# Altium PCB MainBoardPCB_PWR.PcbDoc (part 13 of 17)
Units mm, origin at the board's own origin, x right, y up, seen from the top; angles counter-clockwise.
Board outline 333.63 x 349.38 mm, 16 copper layers (L1, L2 (GND), L3 (Sign), L4 (GND), L5 (Sign), L6 (PWR/GND), L7(PWR/GND), L8 (PWR/GND), L9 (PWR/GND), L10 (PWR/GND), L11 (PWR/GND), L12 (Sign), L13 (GND), L14 (Sign), L15 (GND), L16), stack 2.503 mm thick; 2187 components, 1615 nets, 7987 pads, 1695 vias.
Unrouted connection lines stored in the file: 4757.
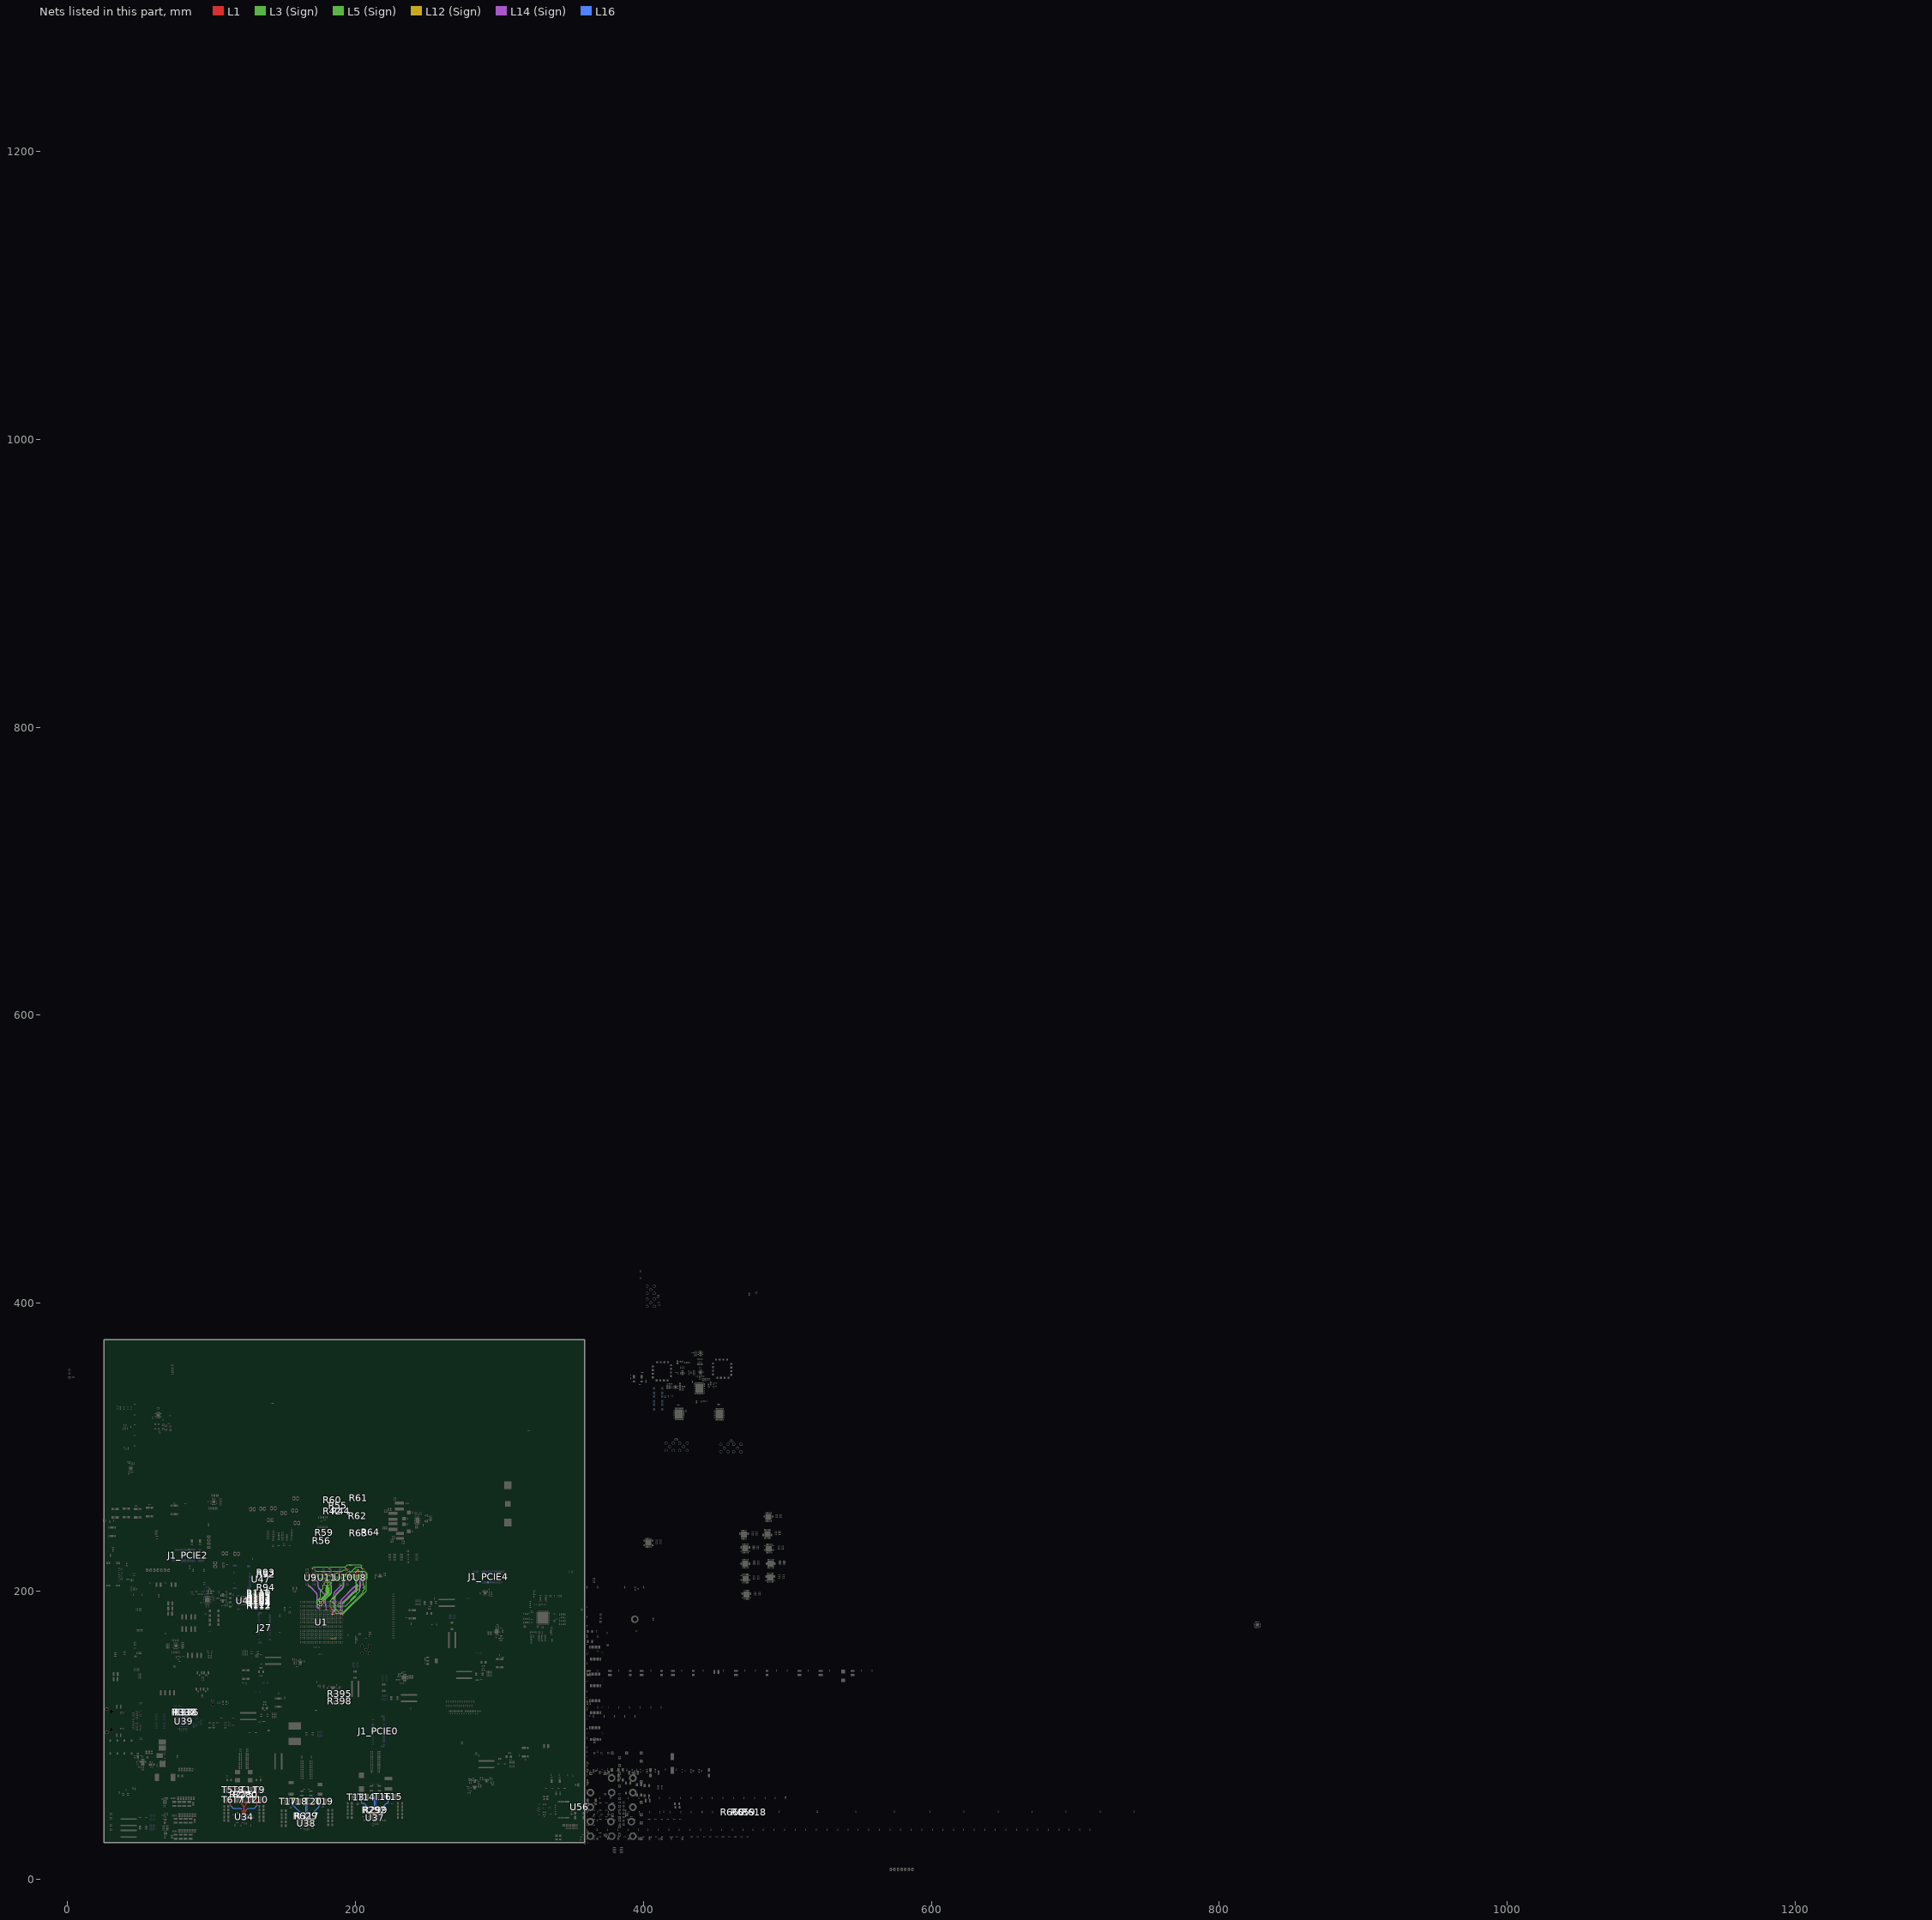
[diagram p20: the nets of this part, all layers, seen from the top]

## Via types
v1: diameter 0.5, hole 0.2, L1 to L16, 786 vias
v2: diameter 0.5/0.35/0.35/0.35/0.35/0.35/0.35/0.35/0.35/0.35/0.35/0.35/0.35/0.35/0.35/0.5 (per signal layer), hole 0.15, L1 to L16, tented both sides, 164 vias
v3: diameter 2.54, hole 1.02, L1 to L16, 152 vias
v4: diameter 0.5/0.35/0.35/0.35/0.35/0.35/0.35/0.35/0.35/0.35/0.35/0.35/0.35/0.35/0.35/0.5 (per signal layer), hole 0.2, L1 to L16, tented both sides, 100 vias
v5: diameter 0.45, hole 0.15, L1 to L16, 79 vias
v6: diameter 0.35/0/0.35 (per signal layer), hole 0.127, L1 to L3 (Sign), tented both sides, 78 vias
v7: diameter 0.45/0.45/0.45/0.45/0.45/0.45/0.45/0.45/0.45/0.45/0.45/0.45/0.45/0.45/0.45/0.45 (per signal layer), hole 0.15, L1 to L16, 65 vias
v8: diameter 0.4, hole 0.15, L1 to L16, 61 vias
v9: diameter 0.2, hole 0.1, L1 to L16, 35 vias
v10: diameter 0.5, hole 0.2, L1 to L16, tented both sides, 32 vias
v11: diameter 0.2/0/0.2 (per signal layer), hole 0.1, L1 to L3 (Sign), 28 vias
v12: diameter 0.4, hole 0.2, L1 to L16, 16 vias
v13: diameter 0.25, hole 0.2, L1 to L16, 16 vias
v14: diameter 0.3, hole 0.2, L1 to L16, 15 vias
v15: diameter 0.5/0.35/0.35/0.35/0.35/0.35/0.35/0.35/0.35/0.35/0.35/0.35/0.35/0.35/0.35/0.45 (per signal layer), hole 0.15, L1 to L16, tented both sides, 10 vias
v16: diameter 5, hole 3, L1 to L16, 9 vias
v17: diameter 0.2/0/0.2 (per signal layer), hole 0.1, L1 to L3 (Sign), tented both sides, 9 vias
v18: diameter 0.35/0/0.35 (per signal layer), hole 0.127, L1 to L3 (Sign), 7 vias
v19: diameter 0.35/0/0.35 (per signal layer), hole 0.127, L14 (Sign) to L16, tented both sides, 5 vias
v20: diameter 1.65, hole 1.65, L1 to L16, 4 vias
v21: diameter 1.15, hole 1.15, L1 to L16, 4 vias
v22: diameter 0.35, hole 0.127, L1 to L2 (GND), 2 vias
v23: diameter 0.4, hole 0.2, L1 to L16, tented both sides, 2 vias
v24: diameter 0.35, hole 0.127, L1 to L2 (GND), tented both sides, 2 vias
v25: diameter 0.508, hole 0.127, L1 to L2 (GND), 2 vias
v26: diameter 0.508, hole 0.127, L2 (GND) to L3 (Sign), 2 vias
v27: diameter 0.35, hole 0.127, L3 (Sign) to L6 (PWR/GND), tented both sides, 2 vias
v28: diameter 0.5, hole 0.2, L3 (Sign) to L6 (PWR/GND), tented both sides, 2 vias
v29: diameter 5.5, hole 3.5, L1 to L16, 1 vias
v30: diameter 0.45/0.45/0.45 (per signal layer), hole 0.15, L1 to L3 (Sign), 1 vias
v31: diameter 0.35/0.35/0.35 (per signal layer), hole 0.127, L1 to L3 (Sign), tented both sides, 1 vias
v32: diameter 0.45/0/0.45 (per signal layer), hole 0.15, L1 to L3 (Sign), tented both sides, 1 vias
v33: diameter 0.45/0/0.45 (per signal layer), hole 0.2, L14 (Sign) to L16, tented both sides, 1 vias
v34: diameter 0.35, hole 0.127, L2 (GND) to L3 (Sign), 1 vias

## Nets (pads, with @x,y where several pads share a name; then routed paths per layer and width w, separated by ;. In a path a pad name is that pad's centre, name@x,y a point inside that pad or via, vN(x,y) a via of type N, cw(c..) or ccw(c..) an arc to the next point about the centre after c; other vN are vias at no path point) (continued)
DDR4_DQ56: U1.R30 U11.A3 | length 13.3
  L1 w0.116: U1.R30@175.927,192.927 v6(175.927,193.616) ; v6(181.467,203.052) 181.47,203.052 U11.A3@181.866,203.448
  L3 (Sign) w0.092: v6(175.927,193.616) 175.976,193.666 176.222,193.666 181.7,199.144 181.7,202.818 v6(181.467,203.052)
DDR4_DQ57: U1.T30 U11.B5 | length 22.9
  L1 w0.116: v6(176.44,193.414) U1.T30@176.927,192.927 ; U11.B5@177.863,204.229 178.26,204.625 v6(178.262,204.625)
  L3 (Sign) w0.092: v6(176.44,193.414) 175.976,192.951 175.404,192.951 175.044,193.311 175.044,193.662 175.553,194.171 176.185,194.171 180.933,198.919 180.933,205.698 179.983,206.648 178.975,206.648 178.714,206.388 178.714,205.077 v6(178.262,204.625)
DDR4_DQ58: U1.P30 U11.C3 | length 15.6
  L1 w0.116: U1.P30@174.927,192.927 v6(175.414,193.414) ; v6(181.467,204.652) 181.47,204.652 U11.C3@181.866,205.048
  L3 (Sign) w0.092: v6(175.414,193.414) 175.414,193.727 175.666,193.979 176.264,193.979 181.508,199.223 181.508,202.248 181.146,202.61 181.146,204.331 v6(181.467,204.652)
DDR4_DQ59: U1.P29 U11.C4 | length 16.9
  L1 w0.116: v6(174.44,192.414) U1.P29@174.927,191.927 ; U11.C4@178.666,205.048 v6(179.063,204.649) v6(179.063,204.649)
  L3 (Sign) w0.092: v6(174.44,192.414) 174.44,192.969 174.649,193.178 174.649,193.856 175.358,194.565 176.036,194.565 180.409,198.938 180.409,203.303 v6(179.063,204.649)
DDR4_DQ60: U1.T28 U11.C2 | length 16.9
  L1 w0.116: U1.T28@176.927,190.927 v6(177.414,191.414) ; U11.C2@182.666,205.048 v6(183.063,204.649) v6(183.063,204.649)
  L3 (Sign) w0.092: v6(177.414,191.414) 177.836,191.836 177.836,192.859 177.703,192.991 177.703,193.727 183.063,199.087 v6(183.063,204.649)
DDR4_DQ61: U1.T27 U11.C5 | length 20.2
  L1 w0.116: v6(176.44,190.414) U1.T27@176.927,189.927 ; v6(177.467,204.652) 177.47,204.652 U11.C5@177.866,205.048
  L3 (Sign) w0.092: v6(176.44,190.414) 176.119,190.093 175.307,190.093 174.86,190.54 173.754,190.54 173.531,190.763 173.531,190.768 173.518,190.782 173.518,191.404 173.339,191.583 173.339,193.469 175.64,195.769 175.64,200.239 177.467,202.067 v6(177.467,204.652)
DDR4_DQ62: U1.P27 U11.D3 | length 21.3
  L1 w0.116: U1.P27@174.927,189.927 v6(175.414,189.44) ; v6(181.467,205.452) 181.47,205.452 U11.D3@181.866,205.848
  L3 (Sign) w0.092: v6(175.414,189.44) 175.876,189.901 176.198,189.901 176.236,189.94 176.668,189.94 176.86,190.132 176.86,190.538 175.933,191.465 175.933,192.424 176.935,193.426 176.935,194.107 181.892,199.064 181.892,205.026 v6(181.467,205.452)
DDR4_DQ63: U1.R27 U11.D4 | length 21.6
  L1 w0.116: v6(175.44,190.414) U1.R27@175.927,189.927 ; U11.D4@178.666,205.848 179.063,206.244 v6(179.065,206.244)
  L3 (Sign) w0.092: 175.044,191.25 175.044,190.81 v6(175.44,190.414) ; 175.044,191.25 175.044,192.964 174.841,193.167 174.841,193.777 175.438,194.373 176.116,194.373 180.734,198.991 180.734,205.626 179.921,206.439 179.259,206.439 v6(179.065,206.244)
DDR4_DQS_0_N: U1.AK21 U8.F3 | length 33
  L1 w0.116: U1.AK21@190.927,183.927 v4(191.414,183.44) ; v2(204.384,207.852) U8.F3@204.787,207.448
  L14 (Sign) w0.105: v4(191.414,183.44) 191.208,183.44 cw(c191.208,183.617) 191.031,183.617 191.031,190.662 cw(c193.571,190.662) 191.774,192.458 199.182,199.865 cw(c200.978,198.069) 200.978,200.609 200.991,200.609 ccw(c200.991,203.099) 202.752,201.338 202.787,201.374 ccw(c200.831,203.33) 203.597,203.33 203.597,207.712 cw(c204.025,207.712) 204.025,208.14 204.095,208.14 cw(c204.095,207.852) v2(204.384,207.852)
DDR4_DQS_0_P: U1.AJ21 U8.G3 | length 33.4
  L1 w0.116: U1.AJ21@189.927,183.927 v4(190.414,183.44) ; v2(204.384,208.652) U8.G3@204.787,208.248
  L14 (Sign) w0.105: v4(190.414,183.44) 190.621,183.44 ccw(c190.621,183.617) 190.798,183.617 190.798,190.662 cw(c193.569,190.662) 191.61,192.621 199.018,200.03 cw(c200.977,198.071) 200.977,200.841 200.99,200.841 ccw(c200.99,203.101) 202.588,201.503 202.621,201.536 ccw(c200.825,203.332) 203.365,203.332 203.365,207.712 cw(c204.025,207.712) 204.025,208.372 204.104,208.372 ccw(c204.104,208.652) v2(204.384,208.652)
DDR4_DQS_1_N: U1.AJ24 U8.A4 | length 23.7
  L1 w0.116: U1.AJ24@189.927,186.927 v4(190.414,187.414) ; U8.A4@201.587,203.448 v2(201.991,203.044)
  L14 (Sign) w0.105: v4(190.414,187.414) 190.179,187.414 cw(c190.179,187.563) 190.031,187.563 190.031,192.623 cw(c192.571,192.623) 190.774,194.419 198.913,202.558 cw(c200.709,200.762) 200.709,203.302 201.734,203.302 cw(c201.734,203.044) v2(201.991,203.044)
DDR4_DQS_1_P: U1.AH24 U8.B4 | length 24.1
  L1 w0.116: U1.AH24@188.927,186.927 v4(189.414,187.414) ; U8.B4@201.587,204.248 v2(201.991,203.844)
  L14 (Sign) w0.105: v4(189.414,187.414) 189.65,187.414 ccw(c189.65,187.563) 189.798,187.563 189.798,192.624 cw(c192.569,192.624) 190.61,194.583 198.749,202.722 cw(c200.708,200.763) 200.708,203.534 201.68,203.534 ccw(c201.68,203.844) v2(201.991,203.844)
DDR4_DQS_2_N: U1.AD21 U10.F3 | length 29.1
  L1 w0.116: v10(184.44,183.44) U1.AD21@184.927,183.927 ; v2(192.923,207.044) U10.F3@193.327,207.448
  L14 (Sign) w0.105: v10(184.44,183.44) 184.314,183.44 cw(c184.314,183.629) 184.125,183.629 184.125,184.417 cw(c185.385,184.417) 184.494,185.308 185.741,186.555 ccw(c185.011,187.286) 186.043,187.286 186.043,196.296 cw(c188.583,196.296) 186.787,198.092 191.365,202.67 ccw(c189.406,204.629) 192.176,204.629 192.176,206.845 cw(c192.672,206.845) 192.672,207.34 cw(c192.672,207.089) 192.923,207.089 v2(192.923,207.044)
DDR4_DQS_2_P: U1.AC21 U10.G3 | length 29.6
  L1 w0.116: v10(183.44,183.44) U1.AC21@183.927,183.927 ; v2(192.923,207.844) U10.G3@193.327,208.248
  L14 (Sign) w0.105: v10(183.44,183.44) 183.703,183.44 ccw(c183.703,183.629) 183.892,183.629 183.892,184.417 cw(c185.384,184.417) 184.329,185.472 185.577,186.719 ccw(c185.01,187.286) 185.811,187.286 185.811,196.297 cw(c188.582,196.297) 186.623,198.256 191.2,202.833 ccw(c189.404,204.63) 191.944,204.63 191.944,206.845 cw(c192.672,206.845) 192.672,207.572 ccw(c192.672,207.824) 192.923,207.824 v2(192.923,207.844)
DDR4_DQS_3_N: U1.AE24 U10.A4 | length 20.3
  L1 w0.116: v4(185.44,187.414) U1.AE24@185.927,186.927 ; U10.A4@190.127,203.448 v2(190.53,203.044)
  L14 (Sign) w0.105: v4(185.44,187.414) 185.24,187.414 cw(c185.24,187.599) 185.056,187.599 185.056,197.649 cw(c187.596,197.649) 185.8,199.445 189.24,202.886 cw(c190.335,201.792) 190.335,203.34 cw(c190.335,203.144) 190.53,203.144 v2(190.53,203.044)
DDR4_DQS_3_P: U1.AD24 U10.B4 | length 20.6
  L1 w0.116: v4(184.44,187.414) U1.AD24@184.927,186.927 ; U10.B4@190.127,204.248 v2(190.53,203.844)
  L14 (Sign) w0.105: v4(184.44,187.414) 184.639,187.414 ccw(c184.639,187.599) 184.823,187.599 184.823,197.65 cw(c187.594,197.65) 185.635,199.609 189.077,203.051 cw(c190.334,201.794) 190.334,203.572 ; 190.335,203.572 ccw(c190.335,203.767) 190.53,203.767 v2(190.53,203.844)
DDR4_DQS_4_N: U1.W25 U9.F3 | length 26.8
  L1 w0.116: v2(170.002,207.044) U9.F3@170.406,207.448 ; v10(179.44,187.44) U1.W25@179.927,187.927
  L14 (Sign) w0.105: v2(170.002,207.044) cw(c170.273,207.044) 170.273,207.315 172.272,207.315 cw(c172.272,205.537) 174.05,205.537 174.05,203.308 ccw(c176.82,203.308) 174.861,201.349 178.183,198.028 cw(c176.387,196.232) 178.927,196.232 178.927,191.109 ccw(c180.587,191.109) 179.413,189.935 179.414,189.933 cw(c178.457,188.976) 179.811,188.976 179.811,187.811 cw(c179.44,187.811) v10(179.44,187.44)
DDR4_DQS_4_P: U1.W24 U9.G3 | length 27.2
  L1 w0.116: v2(170.002,207.844) U9.G3@170.406,208.248 ; U1.W24@179.927,186.927 v10(180.414,187.414)
  L14 (Sign) w0.105: v2(170.002,207.844) ccw(c170.3,207.844) 170.3,207.547 172.272,207.547 cw(c172.272,205.537) 174.282,205.537 174.282,203.309 ccw(c176.822,203.309) 175.026,201.513 178.348,198.191 cw(c176.389,196.233) 179.159,196.233 179.159,191.111 ccw(c180.592,191.111) 179.579,190.098 179.581,190.096 cw(c178.464,188.979) 180.043,188.979 180.043,187.786 ccw(c180.414,187.786) v10(180.414,187.414)
DDR4_DQS_5_N: U1.R25 U9.A4 | length 21.2
  L1 w0.116: U9.A4@167.206,203.448 v2(167.609,203.044) ; v10(175.44,187.44) U1.R25@175.927,187.927
  L14 (Sign) w0.105: v2(167.609,203.044) cw(c167.854,203.044) 167.854,203.289 167.927,203.289 cw(c167.927,202.756) 168.304,203.133 172.557,198.88 cw(c170.761,197.084) 173.301,197.084 173.301,188.865 ccw(c173.85,188.865) 173.85,188.316 173.937,188.316 cw(c173.937,187.538) 174.486,188.088 174.488,188.086 ccw(c175.153,188.751) 175.153,187.811 175.171,187.811 cw(c175.171,187.542) 175.44,187.542 v10(175.44,187.44)
DDR4_DQS_5_P: U1.P25 U9.B4 | length 21.2
  L1 w0.116: U9.B4@167.206,204.248 v2(167.609,203.844) ; U1.P25@174.927,187.927 v10(175.414,188.414)
  L14 (Sign) w0.105: v2(167.609,203.844) 167.609,203.839 ccw(c167.927,203.839) 167.927,203.521 cw(c167.927,202.756) 168.468,203.297 172.721,199.044 cw(c170.763,197.085) 173.533,197.085 173.533,188.865 ccw(c173.85,188.865) 173.85,188.548 173.937,188.548 cw(c173.937,187.539) 174.65,188.252 ccw(c175.155,188.757) 175.155,188.043 175.171,188.043 ccw(c175.171,188.286) 175.414,188.286 v10(175.414,188.414)
DDR4_DQS_6_N: U1.V29 U11.F3 | length 21.4
  L1 w0.116: v1(178.44,192.414) U1.V29@178.927,191.927 ; v2(181.463,207.044) U11.F3@181.866,207.448
  L5 (Sign) w0.105: v1(178.44,192.414) 178.275,192.414 cw(c178.275,192.634) 178.056,192.634 178.056,193.815 cw(c178.576,193.815) 178.576,194.335 ccw(c178.576,195.953) 179.72,194.809 182.783,197.873 ccw(c180.824,199.832) 183.595,199.832 183.595,204.835 ccw(c182,204.835) 182,206.429 181.365,206.429 cw(c181.365,206.858) 180.937,206.858 180.937,207.086 cw(c181.178,207.086) 181.178,207.327 181.18,207.327 cw(c181.18,207.044) v2(181.463,207.044)
DDR4_DQS_6_P: U1.U29 U11.G3 | length 21.8
  L1 w0.116: v6(177.44,192.414) U1.U29@177.927,191.927 ; v2(181.463,207.844) U11.G3@181.866,208.248
  L5 (Sign) w0.105: v6(177.44,192.414) 177.605,192.414 ccw(c177.605,192.633) 177.824,192.633 177.824,193.816 cw(c178.575,193.816) 178.575,194.568 ccw(c178.575,195.956) 179.556,194.974 182.619,198.036 ccw(c180.823,199.833) 183.363,199.833 183.363,204.835 ccw(c182,204.835) 182,206.197 181.365,206.197 cw(c181.365,206.858) 180.705,206.858 180.705,207.086 cw(c181.178,207.086) 181.178,207.56 ccw(c181.178,207.844) v2@181.463,207.844
  other v1: 177.44,192.414
DDR4_DQS_7_N: U1.R29 U11.A4 | length 15.2
  L1 w0.116: v6(175.44,192.414) U1.R29@175.927,191.927 ; U11.A4@178.666,203.448 v2(179.07,203.044)
  L5 (Sign) w0.105: v6(175.44,192.414) ccw(c175.824,192.414) 175.824,192.031 175.927,192.031 ccw(c175.927,192.25) 176.147,192.25 176.147,192.909 cw(c178.918,192.909) 176.958,194.868 178.948,196.858 ccw(c177.152,198.654) 179.692,198.654 179.692,202.908 ccw(c179.286,202.908) 179.286,203.314 ccw(c179.286,203.098) 179.07,203.098 v2(179.07,203.044)
  other v1: 175.44,192.414
DDR4_DQS_7_P: U1.R28 U11.B4 | length 16
  L1 w0.116: v6(175.44,191.414) U1.R28@175.927,190.927 ; U11.B4@178.666,204.248 v2(179.07,203.844)
  L5 (Sign) w0.105: v6(175.44,191.414) cw(c175.824,191.414) 175.824,191.798 175.927,191.798 ccw(c175.927,192.25) 176.379,192.25 176.379,192.909 cw(c178.919,192.909) 177.123,194.705 179.113,196.695 ccw(c177.154,198.654) 179.924,198.654 179.924,202.908 ccw(c179.286,202.908) 179.286,203.546 cw(c179.286,203.763) 179.07,203.763 v2(179.07,203.844)
  other v1: 175.44,191.414
DDR4_DQS_8_N: U1.AA28
DDR4_DQS_8_P: U1.Y28
DDR4_DQS_ODT0: R44.1 U1.AB30 U8.K3 U9.K3 U10.K3 U11.K3 | length 93.1
  L1 w0.116: v2(170.002,210.244) U9.K3@170.406,210.648 ; v2(181.463,210.244) U11.K3@181.866,210.648 ; U1.AB30@182.927,192.927 v6(183.414,192.44) ; U10.K3@193.327,210.648 v2@193.516,210.459 ; U8.K3@204.787,210.648 v2(205.191,210.244)
  L5 (Sign) w0.092: v2(170.002,210.244) 170.318,210.244 170.729,210.655 171.727,210.655 172.084,211.012 172.434,211.012 174.481,208.966 179.565,208.966 179.603,209.004 179.882,209.004 181.122,210.244 v2(181.463,210.244) 182.096,210.244 182.507,210.655 183.793,210.655 185.38,209.067 191.346,209.067 191.954,209.676 192.28,209.676 192.849,210.244 193.239,210.244 193.65,210.655 194.648,210.655 194.867,210.436 194.867,210.022 195.224,209.664 196.736,209.664 197.241,209.664 cw(c197.241,209.575) 197.331,209.575 197.331,209.3 ccw(c197.42,209.3) 197.42,209.21 197.689,209.21 ccw(c197.689,209.3) 197.778,209.3 197.778,209.664 197.778,209.884 cw(c197.868,209.884) 197.868,209.973 198.137,209.973 cw(c198.137,209.884) 198.226,209.884 198.226,209.664 198.226,209.3 ccw(c198.316,209.3) 198.316,209.21 198.584,209.21 ccw(c198.584,209.3) 198.674,209.3 198.674,209.664 198.674,210.029 cw(c198.764,210.029) 198.764,210.119 199.032,210.119 cw(c199.032,210.029) 199.122,210.029 199.122,209.664 199.122,209.3 ccw(c199.211,209.3) 199.211,209.21 199.48,209.21 ccw(c199.48,209.3) 199.57,209.3 199.57,209.575 cw(c199.659,209.575) 199.659,209.664 199.793,209.664 200.959,210.83 204.605,210.83 v2(205.191,210.244)
  L3 (Sign) w0.092: v6(183.414,192.44) 183.774,192.799 184.509,192.799 184.735,192.573 184.735,191.869 185.953,190.652 185.953,190.095 185.599,189.742 185.414,189.742 185.226,189.553 185.226,189.288 185.811,188.703 185.811,188.136 188.33,185.617 191.909,185.617 205.135,198.844 205.135,200.054 206.388,201.307 206.388,201.861 206.388,202.159 ccw(c206.288,202.159) 206.288,202.258 205.743,202.258 cw(c205.743,202.358) 205.643,202.358 205.643,202.556 cw(c205.743,202.556) 205.743,202.655 206.288,202.655 ccw(c206.288,202.755) 206.388,202.755 206.388,203.052 206.388,203.251 205.511,204.127 205.511,209.062 205.702,209.253 205.702,209.733 v2(205.191,210.244)
  other v2: 193.516,210.458
DDR4_DQS_ODT1: U1.AC29
DDR4_PARITY: R42.1 U1.AB26 U8.T3 U9.T3 U10.T3 U11.T3 | length 91.1
  L1 w0.116: v2(170.002,215.852) U9.T3@170.406,215.448 ; v2(181.463,215.852) U11.T3@181.866,215.448 ; v6(182.44,189.414) U1.AB26@182.927,188.927 ; v2(192.923,215.852) U10.T3@193.327,215.448 ; v15(204.384,215.852) U8.T3@204.787,215.448
  L5 (Sign) w0.092: v2(170.002,215.852) 170.854,216.703 172.446,216.703 172.634,216.891 179.786,216.891 179.973,216.703 180.611,216.703 v2(181.463,215.852) 182.314,216.703 183.907,216.703 184.094,216.891 191.246,216.891 191.434,216.703 192.072,216.703 v2(192.923,215.852) 192.923,216.736 194.437,218.249 195.364,218.249 195.498,218.249 ccw(c195.498,218.339) 195.588,218.339 195.588,218.416 cw(c195.678,218.416) 195.678,218.506 195.946,218.506 cw(c195.946,218.416) 196.036,218.416 196.036,218.249 196.036,218.083 ccw(c196.125,218.083) 196.125,217.993 196.394,217.993 ccw(c196.394,218.083) 196.484,218.083 196.484,218.249 196.484,218.416 cw(c196.573,218.416) 196.573,218.506 196.842,218.506 cw(c196.842,218.416) 196.931,218.416 196.931,218.249 196.931,218.083 ccw(c197.021,218.083) 197.021,217.993 197.29,217.993 ccw(c197.29,218.083) 197.379,218.083 197.379,218.16 cw(c197.469,218.16) 197.469,218.249 199.098,218.249 203.721,218.249 204.384,217.587 v15(204.384,215.852)
  L3 (Sign) w0.092: v6(182.44,189.414) 182.709,189.684 182.709,193.373 183.524,194.187 183.789,194.452 ccw(c183.719,194.523) 183.789,194.593 183.677,194.705 cw(c183.747,194.775) 183.677,194.845 183.817,194.986 cw(c183.887,194.916) 183.958,194.986 184.14,194.803 184.544,194.399 ccw(c184.615,194.469) 184.685,194.399 184.825,194.539 ccw(c184.755,194.609) 184.825,194.68 184.421,195.084 184.238,195.267 cw(c184.308,195.337) 184.238,195.407 184.379,195.547 cw(c184.449,195.477) 184.519,195.547 184.702,195.365 185.067,194.999 ccw(c185.137,195.069) 185.208,194.999 185.348,195.139 ccw(c185.278,195.209) 185.348,195.28 184.982,195.645 184.8,195.828 cw(c184.87,195.898) 184.8,195.968 184.94,196.109 cw(c185.01,196.038) 185.08,196.109 185.263,195.926 185.608,195.582 ccw(c185.678,195.652) 185.748,195.582 185.888,195.722 ccw(c185.818,195.792) 185.888,195.862 185.544,196.207 185.361,196.389 cw(c185.431,196.46) 185.361,196.53 185.502,196.67 cw(c185.572,196.6) 185.642,196.67 185.754,196.558 ccw(c185.824,196.628) 185.895,196.558 186.105,196.768 186.245,196.909 191.467,202.13 191.467,209.68 192.176,210.39 192.176,211.402 192.736,211.962 195.66,211.962 200.589,216.891 203.344,216.891 v15(204.384,215.852)
DDR4_RAM_RST_N: R60.1 U1.AB25 U8.P1 U9.P1 U10.P1 U11.P1 | length 96.9
  L1 w0.116: U9.P1@172.006,213.848 v6(172.409,214.252) ; U1.AB25@182.927,187.927 v6(183.414,188.414) ; U11.P1@183.466,213.848 v6(183.87,214.252) ; U10.P1@194.927,213.848 v1(195.33,214.252) ; U8.P1@206.387,213.848 v2(206.791,213.444)
  L12 (Sign) w0.092: v1(195.33,214.252) 195.904,213.677 200.653,213.677 200.749,213.773 201.511,213.773 201.645,213.773 ccw(c201.645,213.862) 201.735,213.862 201.735,214.597 cw(c201.824,214.597) 201.824,214.687 202.093,214.687 cw(c202.093,214.597) 202.183,214.597 202.183,213.773 202.183,213.739 ccw(c202.272,213.739) 202.272,213.649 202.541,213.649 ccw(c202.541,213.739) 202.63,213.739 cw(c202.664,213.739) 202.664,213.773 203.111,213.773 206.193,213.773 206.521,213.444 v2(206.791,213.444)
  L3 (Sign) w0.092: v6(172.409,214.252) 172.755,213.906 183.524,213.906 v6(183.87,214.252) 184.33,213.792 191.033,213.792 191.033,213.864 191.818,214.648 194.934,214.648 v1(195.33,214.252) ; v6(183.414,188.414) 183.414,187.629 184.226,186.817 184.587,186.817 185.811,185.593 185.811,185.136 186.136,184.81 187.261,184.81 192.18,184.811 192.219,184.849 192.227,184.849 207.645,200.268 207.645,205.372 207.645,208.322 ccw(c207.546,208.322) 207.546,208.422 207.206,208.422 cw(c207.206,208.521) 207.107,208.521 207.107,208.719 cw(c207.206,208.719) 207.206,208.819 207.645,208.819 208.084,208.819 ccw(c208.084,208.918) 208.183,208.918 208.183,209.116 ccw(c208.084,209.116) 208.084,209.216 207.645,209.216 207.206,209.216 cw(c207.206,209.315) 207.107,209.315 207.107,209.513 cw(c207.206,209.513) 207.206,209.613 207.645,209.613 208.084,209.613 ccw(c208.084,209.712) 208.183,209.712 208.183,209.91 ccw(c208.084,209.91) 208.084,210.01 207.645,210.01 207.206,210.01 cw(c207.206,210.109) 207.107,210.109 207.107,210.307 cw(c207.206,210.307) 207.206,210.407 207.645,210.407 208.084,210.407 ccw(c208.084,210.506) 208.183,210.506 208.183,210.704 ccw(c208.084,210.704) 208.084,210.804 207.645,210.804 207.206,210.804 cw(c207.206,210.903) 207.107,210.903 207.107,211.101 cw(c207.206,211.101) 207.206,211.201 207.645,211.201 208.084,211.201 ccw(c208.084,211.3) 208.183,211.3 208.183,211.498 ccw(c208.084,211.498) 208.084,211.598 207.645,211.598 207.206,211.598 cw(c207.206,211.697) 207.107,211.697 207.107,211.895 cw(c207.206,211.895) 207.206,211.995 207.645,211.995 208.084,211.995 ccw(c208.084,212.094) 208.183,212.094 208.183,212.292 ccw(c208.084,212.292) 208.084,212.392 207.744,212.392 cw(c207.744,212.491) 207.645,212.491 207.645,212.59 v2(206.791,213.444)
DDR4_RAS: R59.1 U1.AH27 U8.L5 U9.L5 U10.L5 U11.L5 | length 90.7
  L1 w0.116: U9.L5@166.406,211.448 166.802,211.844 v2(166.805,211.844) ; U11.L5@177.866,211.448 178.263,211.844 v2(178.265,211.844) ; U1.AH27@188.927,189.927 v6(189.414,190.414) ; U10.L5@189.327,211.448 189.723,211.844 v2(189.726,211.844) ; U8.L5@200.787,211.448 201.184,211.844 v1(201.186,211.844)
  L12 (Sign) w0.092: 165.884,212.248 166.288,211.844 ; v2@166.802,211.844 166.288,211.844 ; v2(178.265,211.844) v2@178.507,211.844 ; v2(189.726,211.844) 189.988,211.844 ; v1(201.186,211.844) 200.745,211.844 200.241,211.341 200.107,211.341 ccw(c200.107,211.251) 200.018,211.251 200.018,211.15 cw(c199.928,211.15) 199.928,211.06 199.659,211.06 cw(c199.659,211.15) 199.57,211.15 199.57,211.341 199.57,211.532 ccw(c199.48,211.532) 199.48,211.621 199.212,211.621 ccw(c199.212,211.532) 199.122,211.532 199.122,211.43 cw(c199.032,211.43) 199.032,211.341 198.895,211.341 198.76,211.341 ccw(c198.76,211.251) 198.671,211.251 198.671,211.15 cw(c198.581,211.15) 198.581,211.06 198.313,211.06 cw(c198.313,211.15) 198.223,211.15 198.223,211.341 198.223,211.532 ccw(c198.133,211.532) 198.133,211.621 197.865,211.621 ccw(c197.865,211.532) 197.775,211.532 197.775,211.43 cw(c197.686,211.43) 197.686,211.341 197.294,211.341 191.552,211.341 191.017,211.876 190.728,212.165 190.309,212.165 189.988,211.844 ; 166.288,211.844 167.067,211.844 ; 166.288,211.844 v2(166.805,211.844) 167.067,211.844 ; 167.067,211.844 167.388,212.165 167.807,212.165 168.097,211.876 177.793,211.876 177.824,211.844 v2@178.507,211.844 ; v2@178.507,211.844 178.879,212.217 179.692,212.217 180.097,211.812 184.952,211.812 185.839,212.7 188.354,212.7 189.209,211.844 189.988,211.844
  L3 (Sign) w0.092: v6@189.459,190.459 189.459,190.839 189.46,190.84 189.46,190.917 189.462,190.919 189.462,191.101 189.762,191.401 189.762,191.461 190.202,191.901 190.468,191.901 192.179,191.901 192.375,192.098 192.456,192.411 192.729,192.684 193.407,193.362 ccw(c193.322,193.447) 193.407,193.532 193.272,193.667 cw(c193.357,193.752) 193.272,193.837 193.527,194.091 cw(c193.612,194.006) 193.697,194.091 193.916,193.871 193.957,193.83 ccw(c194.042,193.915) 194.127,193.83 194.382,194.085 ccw(c194.297,194.17) 194.382,194.255 194.341,194.296 194.121,194.516 cw(c194.206,194.601) 194.121,194.685 194.376,194.94 cw(c194.461,194.855) 194.545,194.94 194.765,194.72 194.806,194.679 ccw(c194.891,194.764) 194.976,194.679 195.231,194.934 ccw(c195.146,195.018) 195.231,195.103 195.19,195.145 194.97,195.364 cw(c195.055,195.449) 194.97,195.534 195.224,195.789 cw(c195.309,195.704) 195.394,195.789 195.614,195.569 195.656,195.527 ccw(c195.741,195.611) 195.826,195.527 196.081,195.781 ccw(c195.996,195.866) 196.081,195.951 196.038,195.993 195.819,196.213 cw(c195.903,196.298) 195.819,196.383 196.073,196.638 cw(c196.158,196.553) 196.243,196.638 196.463,196.418 196.506,196.375 ccw(c196.591,196.46) 196.676,196.375 196.93,196.629 ccw(c196.845,196.714) 196.93,196.799 196.887,196.842 196.667,197.062 cw(c196.752,197.147) 196.667,197.232 196.922,197.486 cw(c197.007,197.402) 197.092,197.486 197.312,197.267 197.356,197.223 ccw(c197.441,197.307) 197.526,197.223 197.78,197.477 ccw(c197.695,197.562) 197.78,197.647 197.736,197.691 197.516,197.911 cw(c197.601,197.996) 197.516,198.081 197.771,198.335 cw(c197.856,198.25) 197.941,198.335 198.161,198.115 198.205,198.071 ccw(c198.29,198.156) 198.375,198.071 198.63,198.325 ccw(c198.545,198.41) 198.63,198.495 198.585,198.54 198.365,198.76 cw(c198.45,198.845) 198.365,198.929 198.62,199.184 cw(c198.705,199.099) 198.789,199.184 199.009,198.964 199.055,198.918 ccw(c199.14,199.003) 199.225,198.918 199.479,199.173 ccw(c199.395,199.258) 199.479,199.343 199.434,199.389 199.403,199.419 cw(c199.488,199.504) 199.403,199.589 199.658,199.844 cw(c199.743,199.759) 199.828,199.844 199.858,199.813 200.257,199.415 ccw(c200.341,199.499) 200.426,199.415 200.681,199.669 ccw(c200.596,199.754) 200.681,199.839 200.367,200.153 cw(c200.452,200.237) 200.367,200.322 200.495,200.45 200.744,200.45 200.8,200.506 200.8,200.635 cw(c200.888,200.635) 200.888,200.723 201.301,200.723 ccw(c201.301,200.843) 201.421,200.843 201.421,201.203 ccw(c201.301,201.203) 201.301,201.323 200.8,201.323 200.352,201.323 cw(c200.352,201.443) 200.232,201.443 200.232,201.803 cw(c200.352,201.803) 200.352,201.923 200.8,201.923 201.301,201.923 ccw(c201.301,202.043) 201.421,202.043 201.421,202.403 ccw(c201.301,202.403) 201.301,202.524 200.8,202.524 200.352,202.524 cw(c200.352,202.644) 200.232,202.644 200.232,203.004 cw(c200.352,203.004) 200.352,203.124 200.8,203.124 201.301,203.124 ccw(c201.301,203.244) 201.421,203.244 201.421,203.604 ccw(c201.301,203.604) 201.301,203.724 200.92,203.724 cw(c200.92,203.844) 200.8,203.844 200.8,204.204 cw(c200.92,204.204) 200.92,204.324 201.301,204.324 ccw(c201.301,204.444) 201.421,204.444 201.421,204.804 ccw(c201.301,204.804) 201.301,204.924 200.92,204.924 cw(c200.92,205.044) 200.8,205.044 200.8,205.525 ccw(c200.8,205.577) 200.853,205.577 200.853,206.072 ccw(c200.8,206.072) 200.8,206.125 200.325,206.125 cw(c200.325,206.245) 200.205,206.245 200.205,206.605 cw(c200.325,206.605) 200.325,206.725 200.8,206.725 201.301,206.725 ccw(c201.301,206.845) 201.421,206.845 201.421,207.205 ccw(c201.301,207.205) 201.301,207.325 200.8,207.325 cw(c200.8,207.43) 200.695,207.43 200.695,207.821 cw(c200.8,207.821) 200.8,207.925 200.8,208.405 ccw(c200.68,208.405) 200.68,208.526 200.666,208.526 cw(c200.666,208.646) 200.546,208.646 200.546,209.006 cw(c200.666,209.006) 200.666,209.126 200.8,209.126 201.301,209.126 ccw(c201.301,209.246) 201.421,209.246 201.421,209.606 ccw(c201.301,209.606) 201.301,209.726 200.8,209.726 200.676,209.726 cw(c200.676,209.846) 200.556,209.846 200.556,210.206 cw(c200.676,210.206) 200.676,210.326 200.68,210.326 ccw(c200.68,210.446) 200.8,210.446 200.8,210.926 200.8,211.226 200.8,211.458 v1(201.186,211.844)
DDR4_TEN: R56.1 U8.N6 U9.N6 U10.N6 U11.N6
DDR4_WE: R55.1 U1.AG29 U8.L2 U9.L2 U10.L2 U11.L2 | length 94.3
  L1 w0.116: U9.L2@171.206,211.448 v2(171.609,211.044) ; U11.L2@182.666,211.448 v2(183.07,211.044) ; U1.AG29@187.927,191.927 188.341,191.513 v6(188.341,191.476) ; U10.L2@194.127,211.448 v2(194.53,211.044) ; v2(205.184,211.852) U8.L2@205.587,211.448
  L5 (Sign) w0.092: 170.445,210.642 170.847,211.044 v2(171.609,211.044) 171.659,211.094 171.895,211.094 172.005,211.204 172.514,211.204 174.522,209.196 179.802,209.196 181.33,210.723 181.596,210.723 181.629,210.756 181.975,210.756 182.263,211.044 ; v2(205.184,211.852) 204.846,211.852 204.016,211.022 200.879,211.022 200.436,210.578 200.431,210.578 200.253,210.58 198.373,210.597 cw(c198.374,210.666) 198.305,210.666 198.308,210.921 ccw(c198.218,210.922) 198.219,211.011 197.95,211.014 ccw(c197.949,210.924) 197.86,210.925 197.857,210.602 197.854,210.242 cw(c197.764,210.243) 197.763,210.153 197.494,210.156 cw(c197.495,210.245) 197.406,210.246 197.409,210.606 197.412,210.921 ccw(c197.322,210.922) 197.323,211.011 197.054,211.014 ccw(c197.054,210.924) 196.964,210.925 196.961,210.61 196.958,210.25 cw(c196.868,210.251) 196.868,210.162 196.599,210.164 cw(c196.6,210.254) 196.51,210.254 196.513,210.614 196.516,210.921 ccw(c196.427,210.922) 196.428,211.011 196.159,211.014 ccw(c196.158,210.924) 196.068,210.925 196.066,210.618 196.062,210.259 cw(c195.973,210.259) 195.972,210.17 195.703,210.172 cw(c195.704,210.262) 195.615,210.263 195.618,210.622 195.621,210.921 ccw(c195.531,210.922) 195.532,211.011 195.263,211.014 ccw(c195.262,210.924) 195.173,210.925 195.171,210.716 cw(c195.081,210.717) 195.081,210.627 194.946,210.628 v2(194.53,211.044) 193.723,211.044 193.458,210.779 193.112,210.779 192.2,209.867 185.032,209.867 183.855,211.044 v2(183.07,211.044) ; 182.263,211.044 v2(183.07,211.044) ; 182.263,211.044 v2(183.07,211.044)
  L3 (Sign) w0.092: v6(188.341,191.476) 188.45,191.476 188.093,191.119 188.093,190.957 187.865,190.729 187.865,189.715 187.927,189.652 187.927,189.198 188.107,189.018 189.649,189.018 189.86,189.23 189.86,189.599 190.122,189.86 193.421,189.86 196.414,192.854 196.525,192.964 cw(c196.595,192.894) 196.665,192.964 196.663,192.966 ; 196.663,192.967 ccw(c196.733,193.037) 196.803,192.967 196.943,193.107 ccw(c196.873,193.177) 196.943,193.247 196.876,193.315 196.521,193.669 cw(c196.592,193.739) 196.521,193.809 196.662,193.95 cw(c196.732,193.88) 196.802,193.95 197.156,193.596 197.224,193.528 ccw(c197.294,193.598) 197.364,193.528 197.505,193.668 ccw(c197.434,193.739) 197.505,193.809 197.437,193.876 197.083,194.231 cw(c197.153,194.301) 197.083,194.371 197.223,194.511 cw(c197.293,194.441) 197.364,194.511 197.718,194.157 197.785,194.089 ccw(c197.856,194.16) 197.926,194.089 198.066,194.23 ccw(c197.996,194.3) 198.066,194.37 197.998,194.438 197.644,194.792 cw(c197.715,194.862) 197.644,194.932 197.785,195.073 cw(c197.855,195.003) 197.925,195.073 198.279,194.719 198.347,194.651 ccw(c198.417,194.721) 198.487,194.651 198.628,194.791 ccw(c198.557,194.861) 198.628,194.932 198.56,194.999 198.206,195.353 cw(c198.276,195.424) 198.206,195.494 198.346,195.634 cw(c198.416,195.564) 198.487,195.634 198.841,195.28 198.906,195.215 ccw(c198.976,195.285) 199.046,195.215 199.187,195.355 ccw(c199.116,195.425) 199.187,195.495 199.121,195.561 198.767,195.915 cw(c198.837,195.985) 198.767,196.055 198.908,196.196 cw(c198.978,196.125) 199.048,196.196 199.402,195.841 199.467,195.776 ccw(c199.537,195.846) 199.608,195.776 199.748,195.917 ccw(c199.678,195.987) 199.748,196.057 199.683,196.122 199.329,196.476 cw(c199.399,196.546) 199.329,196.617 199.469,196.757 cw(c199.539,196.687) 199.609,196.757 199.964,196.403 200.034,196.333 ccw(c200.104,196.403) 200.174,196.333 200.314,196.473 ccw(c200.244,196.543) 200.314,196.613 cw(c200.385,196.684) 200.314,196.754 200.385,196.824 200.385,197.495 203.156,200.266 203.156,211.283 203.429,211.556 203.429,212.319 203.44,212.33 203.44,212.335 203.949,212.844 203.954,212.844 204.166,213.056 204.564,213.056 204.793,212.827 204.793,212.242 v2(205.184,211.852)
DDR4_ZQ: U1.AB23
DDR4_ZQ_1: R61.1 U8.F6
DDR4_ZQ_2: R62.1 U10.F6
DDR4_ZQ_3: R63.1 U9.F6
DDR4_ZQ_4: R64.1 U11.F6
DEVSLP: J27.38
DEVSLP_PCIE0: J1_PCIE0.40 R395.1 U1.AE5
DEVSLP_PCIE1: R398.1 U1.AD4
DEVSLP_PCIE2: J1_PCIE2.40 R618.1 U1.AE4
DEVSLP_PCIE3: R659.1 U1.AB4
DEVSLP_PCIE4: J1_PCIE4.40 R660.1 U1.AC4
DH1: T5.4 T6.4 U34.23 | length 27.2
  L1 w0.254: v9(113.271,51.103) 113.271,57.197 ; T6.4@114.394,56.966 113.502,56.966 113.271,57.197 ; T5.4@114.394,63.966 113.502,63.966 113.271,63.735 113.271,57.197 ; U34.23@121.477,45.406 v9(121.477,48.088)
  L16 w0.254: v9(113.271,51.103) 115.091,49.283 120.283,49.283 v9(121.477,48.088)
DH1_1: T13.4 U37.23 | length 18.9
  L1 w0.254: T13.4@203.243,58.956 203.275,58.988 v9(203.823,58.988) ; U37.23@212.295,44.86 v9(212.295,46.056)
  L16 w0.254: v9(203.823,58.988) 203.823,58.949 204.183,58.589 204.183,52.963 204.459,52.687 205.664,52.687 v9(212.295,46.056)
DH1_2: T17.4 U38.23 | length 18.7
  L1 w0.254: T17.4@156.259,55.86 v8@156.788,55.86 ; v9(164.637,42.818) 164.637,41.232 164.783,41.086 U38.23@164.783,41.015
  L16 w0.254: v8@156.788,55.86 157.093,55.555 157.093,50.965 164.637,43.421 v9(164.637,42.818)
  other v8: 156.837,55.811
DH2: T9.4 T10.4 U34.18 | length 22.7
  L1 w0.254: U34.18@123.977,45.406 123.979,45.408 v9(123.979,47.84) ; T10.4@130.615,53.162 131.392,53.162 131.692,53.462 ; T9.4@130.615,60.156 131.392,60.156 131.692,59.856 131.692,53.462 ; v9(131.692,51.134) 131.692,53.462
  L16 w0.254: v9(123.979,47.84) 123.979,47.935 125.327,49.283 129.841,49.283 v9(131.692,51.134)
DH2_1: T15.4 U37.18 | length 15
  L1 w0.254: U37.18@214.795,44.86 v9(214.795,46.054) ; v9(223.137,55.146) 223.168,55.178 T15.4@223.717,55.178
  L16 w0.254: v9(214.795,46.054) 221.477,52.737 222.565,52.737 222.802,52.974 222.802,54.811 v9(223.137,55.146)
DH2_2: T19.4 U38.18 | length 15
  L1 w0.254: U38.18@167.283,41.015 167.283,41.086 167.429,41.232 v9(167.429,42.744) ; v8@175.269,52.082 175.804,52.082 T19.4@175.872,52.15
  L16 w0.254: v9(167.429,42.744) 174.934,50.249 174.934,51.746 v8@175.269,52.082
  other v8: 175.29,52.083
DIR_CMD: R92.2 U47.A2 | length 4.9
  L16 w0.098: U47.A2@134.639,208.953 134.639,210.287 136.163,211.811 R92.2@137.599,211.811
DIR_DAT0_H: R93.2 U47.A3 | length 5.9
  L16 w0.098: U47.A3@134.239,208.953 134.239,210.477 136.614,212.852 R93.2@137.599,212.852
DIR_DAT1_H: R94.2 U47.E3
DL1: R275.2 T7.4 T8.4 U34.21 | length 20.9
  L1 w0.254: T7.4@121.627,56.966 121.502,56.966 120.752,57.716 ; T8.4@121.627,63.966 121.502,63.966 120.752,63.216 R275.2@120.752,58.572 120.752,57.716 ; U34.21@122.477,45.406 122.477,50.661 120.752,52.386 120.752,57.716
DL1_1: R292.2 T14.4 U37.21 | length 15.5
  L1 w0.254: T14.4@210.829,58.956 211.402,58.956 v9(211.409,58.949) ; v9(213.195,47.396) 213.195,47.346 213.196,47.346 213.196,46.01 213.295,45.911 U37.21@213.295,44.86
  L16 w0.254: v9(211.409,58.949) 213.195,57.163 v9(213.195,47.396)
DL1_2: R629.2 T18.4 U38.21 | length 16.1
  L1 w0.254: T18.4@163.888,55.86 v8(164.693,55.86) ; v9(165.533,43.268) 165.533,42.228 165.783,41.978 U38.21@165.783,41.015
  L16 w0.254: v8(164.693,55.86) 165.533,55.02 v9(165.533,43.268)
DL2: R280.2 T11.4 T12.4 U34.20 | length 16.9
  L1 w0.254: U34.20@122.977,45.406 122.978,50.661 124.227,51.911 124.227,53.906 ; T12.4@123.352,53.156 123.477,53.156 124.227,53.906 ; T11.4@123.352,60.156 123.477,60.156 124.227,59.406 R280.2@124.227,58.572 124.227,53.906
DL2_1: R299.2 T16.4 U37.20 | length 12.5
  L1 w0.254: U37.20@213.795,44.86 213.795,45.836 214.045,46.086 v9(214.045,47.396) ; v9(215.605,55.146) 215.637,55.178 T16.4@216.185,55.178
  L16 w0.254: v9(214.045,47.396) 214.045,54.997 214.194,55.146 v9(215.605,55.146)
DL2_2: R317.2 T20.4 U38.20 | length 12.4
  L1 w0.254: U38.20@166.283,41.015 166.283,42.053 166.458,42.228 v9(166.458,43.143) R317.2@166.458,43.268 ; v8@167.436,52.11 167.976,52.11 T20.4@168.016,52.15
  L16 w0.254: v9(166.458,43.143) 166.458,51.314 167.226,52.082 167.408,52.082 v8@167.436,52.11
  other v8: 167.434,52.111
DS_TCK: U39.20 U56.12
DS_TDI: R336.2 U39.23 U56.14
DS_TDO: R337.2 U39.21 U56.11
DS_TMS: R338.2 U39.22 U56.13
eMMC_clk: R112.2 U41.M6 | length 13.8
  L1 w0.098: v6(130.946,189.598) 132.633,189.598 R112.2@132.646,189.611
  L3 (Sign) w0.098: v17(121.468,193.979) 122.417,194.928 124.552,194.928 129.882,189.598 v6(130.946,189.598)
eMMC_cmd: R111.2 U41.M5 | length 13.3
  L1 w0.098: v6(130.937,190.602) R111.2@132.646,190.602
  L3 (Sign) w0.098: v17(121.468,194.479) 121.687,194.479 122.334,195.126 124.635,195.126 129.159,190.602 v6(130.937,190.602)
eMMC_data0: R105.2 U41.A3 | length 6.2
  L1 w0.098: v6(130.937,196.723) R105.2@132.646,196.723
  L3 (Sign) w0.098: v17(126.968,195.479) 128.212,196.723 v6(130.937,196.723)
eMMC_data1: R107.2 U41.A4 | length 5.8
  L1 w0.098: U41.A4@126.968,194.979 130.363,194.979 130.651,194.691 R107.2@132.646,194.691
eMMC_data2: R108.2 U41.A5 | length 6.4
  L1 w0.098: U41.A5@126.968,194.479 128.088,194.479 129.908,192.659 R108.2@132.646,192.659
eMMC_data3: R110.2 U41.B2 | length 7.3
  L1 w0.098: v32(130.946,198.755) R110.2@132.646,198.755
  L3 (Sign) w0.098: v17(126.468,195.979) 129.244,198.755 v32(130.946,198.755)
eMMC_data4: R101.2 U41.B3 | length 7.1
  L1 w0.098: v17(126.459,195.479) U41.B3@126.468,195.479 ; v6(130.937,197.739) R101.2@132.646,197.739
  L3 (Sign) w0.098: v17(126.459,195.479) 128.427,197.447 128.435,197.447 128.727,197.739 v6(130.937,197.739)
eMMC_data5: R102.2 U41.B4 | length 6.6
  L1 w0.098: v6(130.937,195.707) 130.996,195.707 131.195,195.905 132.448,195.905 R102.2@132.646,195.707
  L3 (Sign) w0.098: v17(126.468,194.979) 127.009,194.979 127.737,195.707 v6(130.937,195.707)
eMMC_data6: R103.2 U41.B5 | length 6.5
  L1 w0.098: v6(130.937,193.675) R103.2@132.646,193.675
  L3 (Sign) w0.098: v17(126.468,194.479) 129.957,194.479 130.761,193.675 v6(130.937,193.675)
eMMC_data7: R104.2 U41.B6 | length 7.1
  L1 w0.098: v6(130.946,191.643) R104.2@132.646,191.643
  L3 (Sign) w0.098: v17(126.468,193.979) 128.093,193.979 130.429,191.643 v6(130.946,191.643)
